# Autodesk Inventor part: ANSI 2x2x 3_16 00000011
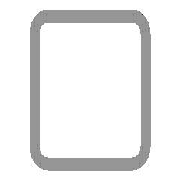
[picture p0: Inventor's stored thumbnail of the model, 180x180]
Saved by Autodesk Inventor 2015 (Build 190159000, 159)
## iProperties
IsCustomPart: 1
Created: 2007-02
Part Number: ANSI 2x2x 3_16 00000011
Material: Steel
Document SubType Name: Modeling
Standard: AISC
Designer: Autodesk, Inc.
Size Designation: 2x2x3/16
Stock Number: 2x2x 3/16
Density: 7.85 g/cm^3
Description: Tube
Standards Organization: ANSI
Language: en-US
Categories: <MemberInstance><Categories><Category DisplayName="Structural Shapes" InternalName="089c4875-fa83-4c05-b084-43b9cc11f5ed" Mnemonic="GRDR"><CategoryParameter Dis
Mass: 4523.85 g
Surface Area: 2436.47 cm^2
Volume: 576.287 cm^3
Appearance: Steel
_FrameMemberDoc: Frame Member File
_Version: 15.0.0
_CCFamilyMember: 1
_CCFamilyDisplayName: ANSI AISC (Square) - Tube
G_L: 27.716 in
G_W: 2.000 in
G_H: 2.000 in
+83F7954C-61D9-450D-8266-2EED88268707+CUTDETAIL1: Cut
Author: Autodesk, Inc.
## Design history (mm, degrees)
node "Start plane"
node "End plane"
sketch "Sketch"
  geometry: L1 (-25.4, -15.875)-(-25.4, 15.875); L2 (-15.875, 25.4)-(15.875, 25.4); L3 (25.4, 15.875)-(25.4, -15.875); L4 (15.875, -25.4)-(-15.875, -25.4); L5 (-15.875, 20.637)-(15.875, 20.638); L6 (20.637, 15.875)-(20.637, -15.875); L7 (15.875, -20.637)-(-15.875, -20.638); L8 (-20.637, -15.875)-(-20.637, 15.875); L9 (0, 38.322)-(0, -38.322) reference; L10 (-38.322, 0)-(38.322, 0) reference; A1 r 9.525 centre (-15.875, -15.875) between (-25.4, -15.875) and (-15.875, -25.4); A2 r 9.525 centre (-15.875, 15.875) between (-15.875, 25.4) and (-25.4, 15.875); A3 r 9.525 centre (15.875, 15.875) between (25.4, 15.875) and (15.875, 25.4); A4 r 9.525 centre (15.875, -15.875) between (15.875, -25.4) and (25.4, -15.875); A5 r 4.762 centre (-15.875, 15.875) between (-15.875, 20.637) and (-20.637, 15.875); A6 r 4.762 centre (15.875, 15.875) between (20.637, 15.875) and (15.875, 20.638); A7 r 4.762 centre (15.875, -15.875) between (15.875, -20.637) and (20.637, -15.875); A8 r 4.762 centre (-15.875, -15.875) between (-20.637, -15.875) and (-15.875, -20.638)
  constraints: 16 end point, 16 point on circle, 8 centre point, 8 tangent, 4 parallel, 3 equal radius, 2 perpendicular, 7 other
  dimensions: "d10" = 50.8 distance between parallel lines of L2 L4 (= G_H); "d11" = 50.8 distance between parallel lines of L1 L3 (= G_W); "d12" = 4.7625 distance between parallel lines of L3 L6 (= G_T); "d15" = 25.4 distance between parallel lines of L2 L10 (= 0.5 x d10); "d16" = 25.4 distance between parallel lines of L9 L3 (= 0.5 x d11); "d17" = 9.525 radius of A1 (= G_IR)
extrude "Body" new body sketch "Sketch" stored distance "d3" = 703.9864 (= G_L); taper "d4" = 0 deg
node "Driven Length"
  sketch "Sketch3"
    geometry: L1 (0, 0)-(10, 0) reference
    constraints: 2 end point, 1 horizontal
  workplane "Work Plane4"
  sketch "Sketch4"
    geometry: L1 (-2, 0)-(12, 0) reference; L2 (-2, 703.986)-(12, 703.986) reference
    dimensions: "d19" = 703.9864 distance between parallel lines of L1 L2 (derived)
workplane "Work Plane3"
split "Split1"
body "Solid1"
other parameters: "G_W" = 50.8 [user parameter; used in 1 equation term], "G_H" = 50.8 [user parameter; used in 1 equation term], "G_T" = 4.7625 [user parameter; used in 1 equation term], "G_IR" = 9.525 [user parameter; used in 1 equation term], "G_L" = 703.9864 (= d19) [user parameter; used in 1 equation term], "G_OFFSET_START" = 0 [user parameter; used in 1 equation term], "G_OFFSET_END" = -50.8 [user parameter; used in 1 equation term], "d13" = 0 (computed from G_OFFSET_START), "d14" = 703.9864 (= G_OFFSET_END + B_L), "B_L" = 754.7864 [user parameter; used in 1 equation term], "d18" = 90 deg
